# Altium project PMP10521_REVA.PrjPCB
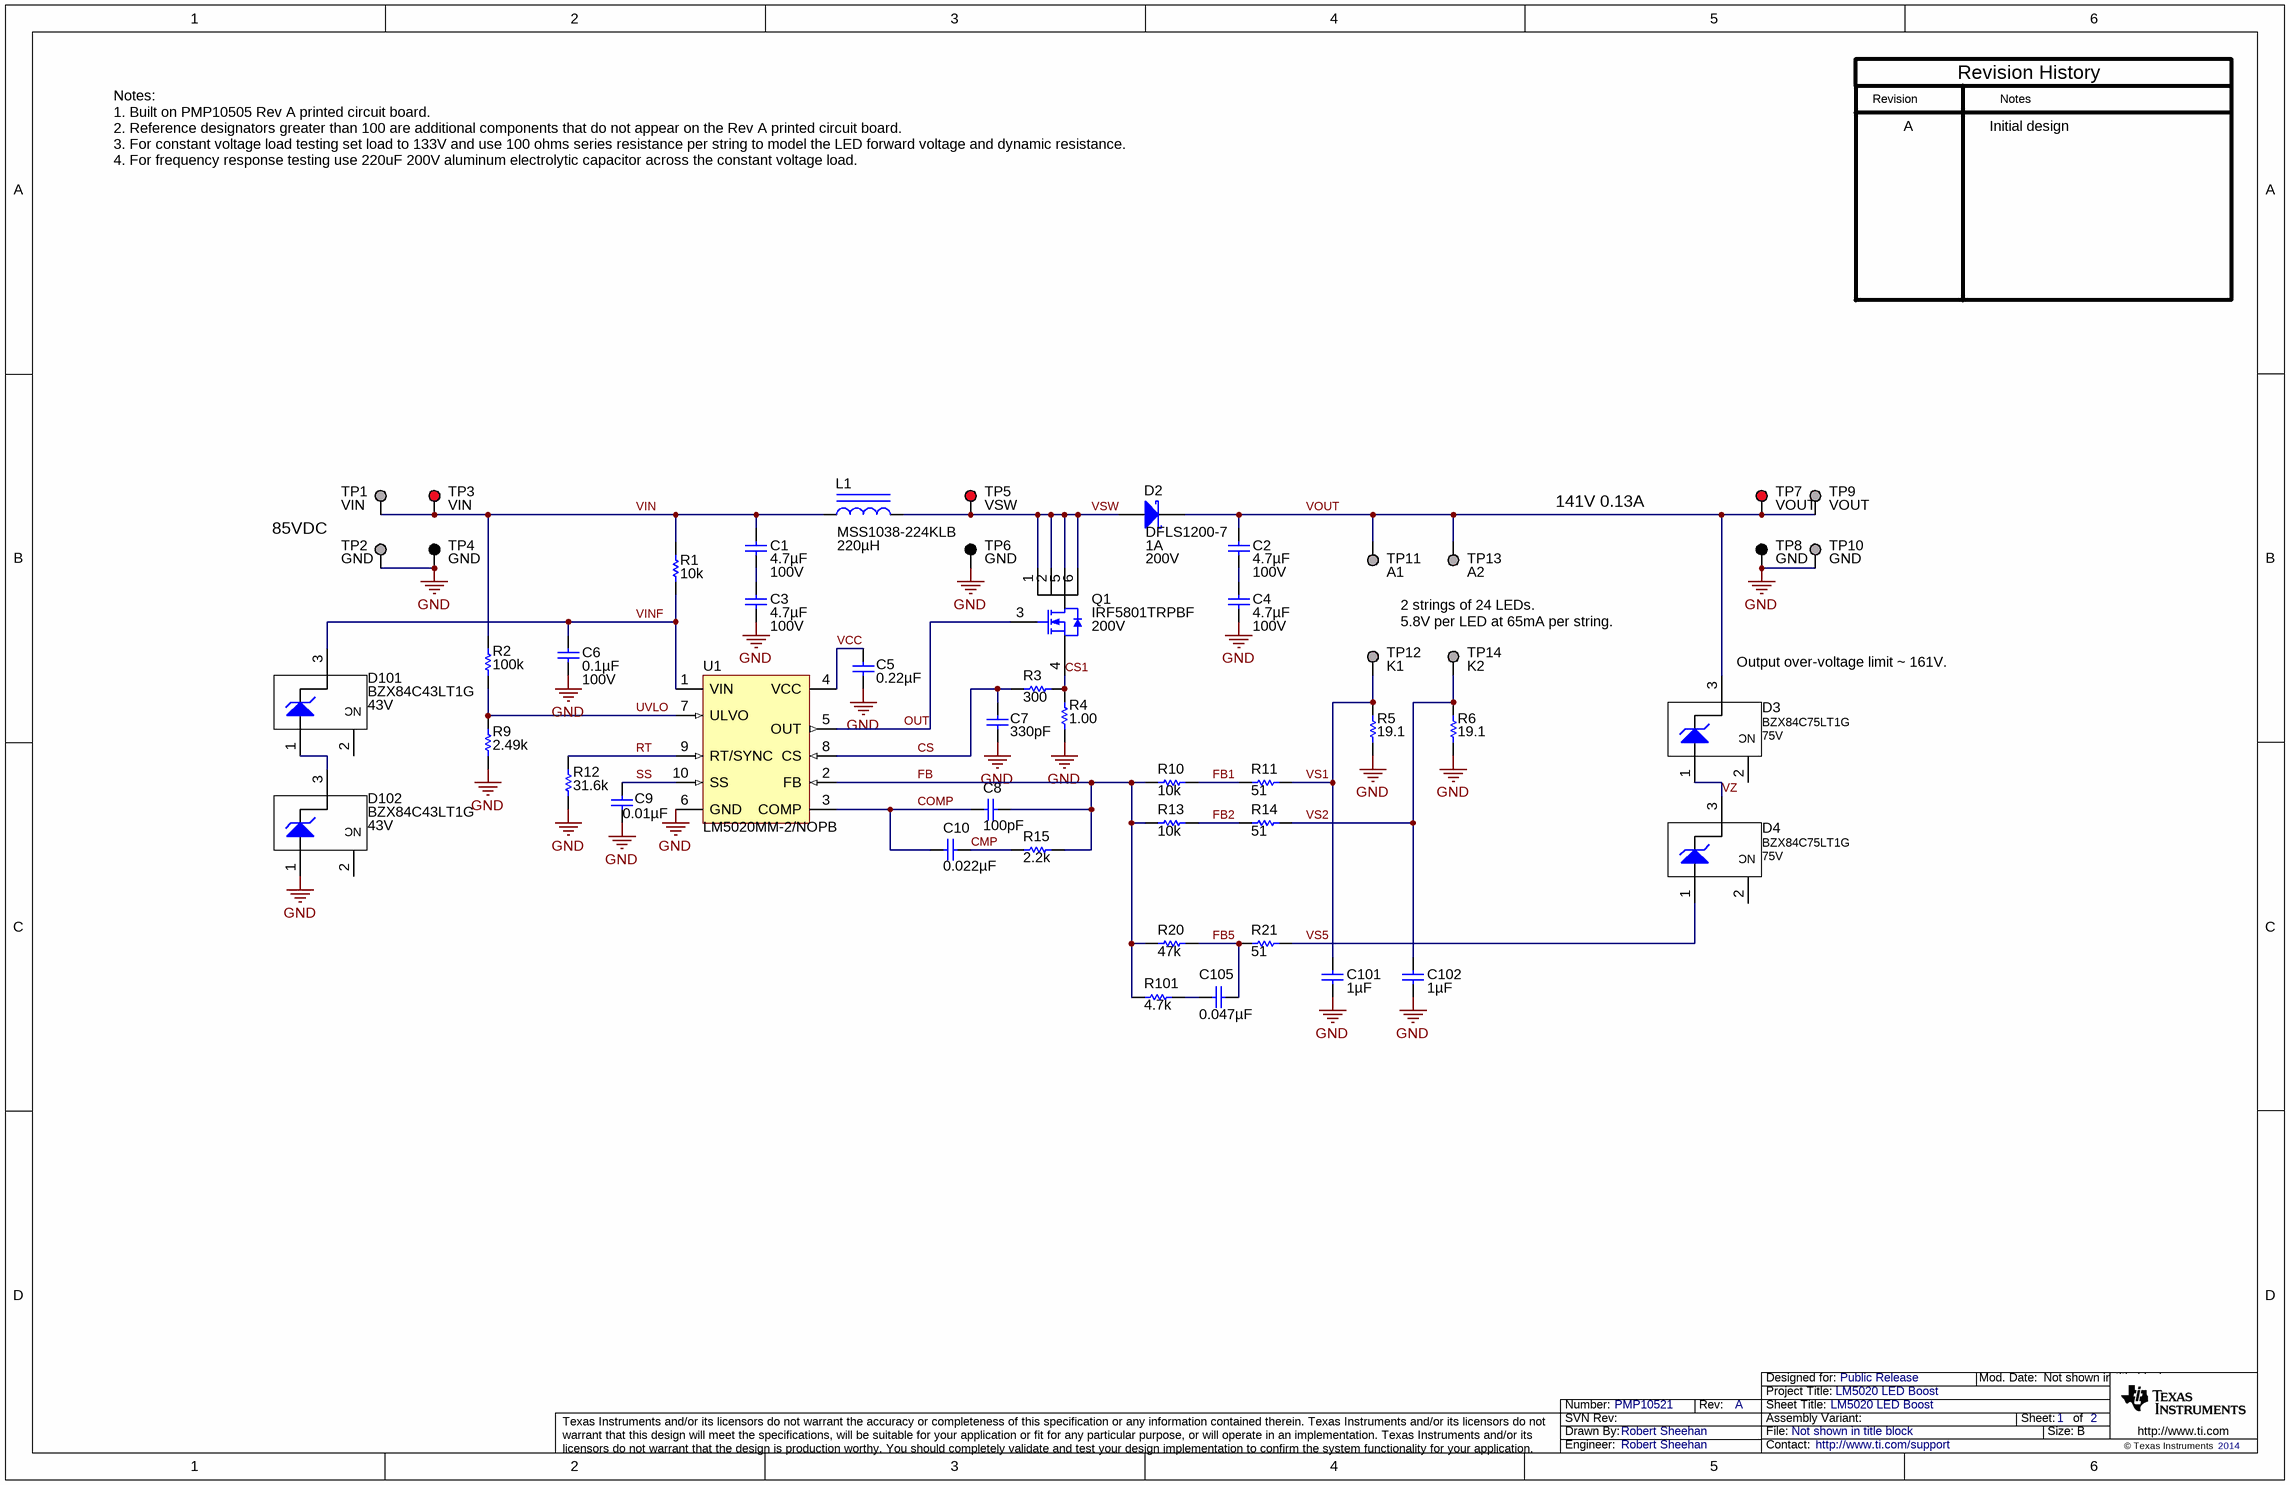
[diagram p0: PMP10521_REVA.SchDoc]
TechSupport: http://www.ti.com/support; SCH_Rev: A; PRJ_Title: LM5020 LED Boost; PRJ_Number: PMP10521; PRJ_Engineer: Robert Sheehan; PRJ_Customer: Public Release; PCB_Rev: A; PCB_Layout: Robert Sheehan; CopyrightYear: 2014
2 sheets, 69 parts. Net scope: global (net labels, ports and power ports of the same name join across sheets).
Board file: PMP10505_REVA.PcbDoc
Sheets:
  PMP10521_REVA.SchDoc
  PMP10521_REVA_Hardware.SchDoc

## Sheet PMP10521_REVA.SchDoc: LM5020 LED Boost
size 431 x 279 mm; Date: Not shown in title block; ApprovedBy: Not shown in title block; CheckedBy: Not shown in title block; Author: Not shown in title block; CompanyName: Not shown in title block; DrawnBy: Robert Sheehan; Engineer: Not shown in title block; Organization: Not shown in title block; Address1: Not shown in title block; Address2: Not shown in title block; Address3: Not shown in title block; Address4: Not shown in title block; DocumentNumber: 1; Revision: Use project parameter SCH_Rev; SheetNumber: 1; SheetTotal: 2; PageSetup: Record=PageOptions|CenterHorizontal=True|CenterVertical=True|PrintScale=1.00|XCorrection=1.00|YCorrection=1.00|PrintKind=0|BorderSize=5000000|LeftOffset=0|BottomOffset=0|Orientation=2|PaperLength=1000|PaperWidth=1000|Scale=100|PaperSource=15|PrintQuality=600|MediaType=1|DitherType=10|PaperKind=Letter|PrintScaleMode=1

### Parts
C1  ValueDisplayed: 4.7µF  Value2: 100V  [1210]  (hidden comment: C3225X7S2A475K200AB)
C2  ValueDisplayed: 4.7µF  Value2: 100V  [1210]  (hidden comment: C3225X7S2A475K200AB)
C3  ValueDisplayed: 4.7µF  Value2: 100V  [1210]  (hidden comment: C3225X7S2A475K200AB)
C4  ValueDisplayed: 4.7µF  Value2: 100V  [1210]  (hidden comment: C3225X7S2A475K200AB)
C5  ValueDisplayed: 0.22µF  [0603]  (hidden comment: GRM188R71C224KA01D)
C6  ValueDisplayed: 0.1µF  Value2: 100V  [0603]  (hidden comment: GRM188R72A104KA35D)
C7  ValueDisplayed: 330pF  [0603]  (hidden comment: GRM188R71H331KA01D)
C8  ValueDisplayed: 100pF  [0603]  (hidden comment: GRM1885C1H101JA01D)
C9  ValueDisplayed: 0.01µF  [0603]  (hidden comment: GRM188R71H103KA01D)
C10  ValueDisplayed: 0.022µF  [0603]  (hidden comment: GRM188R71H223KA01D)
C101  ValueDisplayed: 1µF  [0805_HV]  (hidden comment: GRM21BR71E105KA99L)
C102  ValueDisplayed: 1µF  [0805_HV]  (hidden comment: GRM21BR71E105KA99L)
C105  ValueDisplayed: 0.047µF  [0603]  (hidden comment: GRM188R71H473KA61D)
D2  DFLS1200-7  value 200V  Value1: 1A  [powerDI123]
D3  BZX84C75LT1G  value 75V  [SOT-23]
D4  BZX84C75LT1G  value 75V  [SOT-23]
D101  BZX84C43LT1G  value 43V  [SOT-23]
D102  BZX84C43LT1G  value 43V  [SOT-23]
L1  MSS1038-224KLB  ValueDisplayed: 220µH  [MSS1038]
Q1  IRF5801TRPBF  value 200V  [TSOP-6]
R1  value 10k  [0603]  (hidden comment: CRCW060310K0JNEA)
R2  value 100k  [0603]  (hidden comment: CRCW0603100KFKEA)
R3  value 300  [0603]  (hidden comment: CRCW0603300RJNEA)
R4  value 1.00  [0805_HV]  (hidden comment: CRCW08051R00FKEA)
R5  value 19.1  [1206]  (hidden comment: CRCW120619R1FKEA)
R6  value 19.1  [1206]  (hidden comment: CRCW120619R1FKEA)
R9  value 2.49k  [0603]  (hidden comment: CRCW06032K49FKEA)
R10  value 10k  [0603]  (hidden comment: CRCW060310K0JNEA)
R11  value 51  [0603]  (hidden comment: CRCW060351R0JNEA)
R12  value 31.6k  [0603]  (hidden comment: CRCW060331K6FKEA)
R13  value 10k  [0603]  (hidden comment: CRCW060310K0JNEA)
R14  value 51  [0603]  (hidden comment: CRCW060351R0JNEA)
R15  value 2.2k  [0603]  (hidden comment: CRCW06032K20JNEA)
R20  value 47k  [0603]  (hidden comment: CRCW060347K0JNEA)
R21  value 51  [0603]  (hidden comment: CRCW060351R0JNEA)
R101  value 4.7k  [0603]  (hidden comment: CRCW06034K70JNEA)
TP1  VIN  [Keystone1598-2]
TP2  GND  [Keystone1598-2]
TP3  VIN  [Keystone5010]
TP4  GND  [Keystone5011]
TP5  VSW  [Keystone5010]
TP6  GND  [Keystone5011]
TP7  VOUT  [Keystone5010]
TP8  GND  [Keystone5011]
TP9  VOUT  [Keystone1598-2]
TP10  GND  [Keystone1598-2]
TP11  A1  [Keystone1598-2]
TP12  K1  [Keystone1598-2]
TP13  A2  [Keystone1598-2]
TP14  K2  [Keystone1598-2]
U1  LM5020MM-2/NOPB  [MUB10A_N]

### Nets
GND: C3.2 C4.2 C5.2 C6.2 C7.2 C9.2 C101.2 C102.2 D102.1(A) R4.1 R5.1 R6.1 R9.1 R12.1 TP2.1 TP4.1 TP6.1 TP8.1 TP10.1 U1.6(GND)
CMP: C10.1 R15.1
COMP: C8.2 C10.2 U1.3(COMP)
CS: C7.1 R3.1 U1.8(CS)
CS1: Q1.4(S) R3.2 R4.2
FB: C8.1 R10.1 R13.1 R15.2 R20.1 R101.1 U1.2(FB)
FB1: R10.2 R11.1
FB2: R13.2 R14.1
FB5: C105.1 R20.2 R21.1
OUT: Q1.3(G) U1.5(OUT)
RT: R12.2 U1.9(RT/SYNC)
SS: C9.1 U1.10(SS)
UVLO: R2.1 R9.2 U1.7(ULVO)
VCC: C5.1 U1.4(VCC)
VIN: C1.1 L1.1 R1.2 R2.2 TP1.1 TP3.1
VINF: C6.1 D101.3(K) R1.1 U1.1(VIN)
VOUT: C2.1 D2.1(K) D3.3(K) TP7.1 TP9.1 TP11.1 TP13.1
VS1: C101.1 R5.2 R11.2 TP12.1
VS2: C102.1 R6.2 R14.2 TP14.1
VS5: D4.1(A) R21.2
VSW: D2.2(A) L1.2 Q1.1(D) Q1.2(D) Q1.5(D) Q1.6(D) TP5.1
VZ: D3.1(A) D4.3(K)
NetC1_2: C1.2 C3.1
NetC2_2: C2.2 C4.1
NetC105_2: C105.2 R101.2
NetD101_1: D101.1(A) D102.3(K)

Not connected (* = marked no-connect by the designer): D3 2(NC); D4 2(NC); D101 2(NC); D102 2(NC)

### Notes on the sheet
- Revision
- Notes
- Revision History
- A
- Initial design
- Notes:
  1. Built on PMP10505 Rev A printed circuit board.
  2. Reference designators greater than 100 are additional components that do not appear on the Rev A printed circuit board.
  3. For constant voltage load testing set load to 133V and use 100 ohms series resistance per string to model the LED forward voltage and dynamic resistance.
  4. For frequency response testing use 220uF 200V aluminum electrolytic capacitor across the constant voltage load.
- 141V 0.13A
- 85VDC
- 2 strings of 24 LEDs.
  5.8V per LED at 65mA per string.
- (near D3) Output over-voltage limit ~ 161V.

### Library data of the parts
C1-C4 = C3225X7S2A475K200AB: CAP, CERM, 4.7uF, 100V, +/-10%, X7S, 1210; Manufacturer: TDK; Polarized: N; CompType: Capacitor; U/M: EA; Cap_F: 0.0000047; Tolerance_%: 10; Value1: Unknown; VDC_V: 100; TaMin_C: -55; TaMax_C: 125
C5 = GRM188R71C224KA01D: CAP, CERM, 0.22uF, 16V, +/-10%, X7R, 0603; Manufacturer: MuRata; Polarized: N; CompType: Capacitor; U/M: EA; Cap_F: 0.00000022; Tolerance_%: 10; Value1: Unknown; VDC_V: 16; TaMin_C: -55; TaMax_C: 125
C6 = GRM188R72A104KA35D: CAP, CERM, 0.1uF, 100V, +/-10%, X7R, 0603; Manufacturer: MuRata; Polarized: N; CompType: Capacitor; U/M: EA; Cap_F: 0.0000001; Tolerance_%: 10; Value1: Unknown; VDC_V: 100; TaMin_C: -55; TaMax_C: 125
C7 = GRM188R71H331KA01D: CAP, CERM, 330pF, 50V, +/-10%, X7R, 0603; Manufacturer: MuRata; Polarized: N; CompType: Capacitor; U/M: EA; Cap_F: 0.00000000033; Tolerance_%: 10; Value1: Unknown; VDC_V: 50; TaMin_C: -55; TaMax_C: 125
C8 = GRM1885C1H101JA01D: CAP, CERM, 100pF, 50V, +/-5%, C0G/NP0, 0603; Manufacturer: MuRata; Polarized: N; CompType: Capacitor; U/M: EA; Cap_F: 0.0000000001; Tolerance_%: 5; Value1: Unknown; VDC_V: 50; TaMin_C: -55; TaMax_C: 125
C9 = GRM188R71H103KA01D: CAP, CERM, 0.01uF, 50V, +/-10%, X7R, 0603; Manufacturer: MuRata; Polarized: N; CompType: Capacitor; U/M: EA; Cap_F: 0.00000001; Tolerance_%: 10; Value1: Unknown; VDC_V: 50; TaMin_C: -55; TaMax_C: 125
C10 = GRM188R71H223KA01D: CAP, CERM, 0.022uF, 50V, +/-10%, X7R, 0603; Manufacturer: MuRata; Polarized: N; CompType: Capacitor; U/M: EA; Cap_F: 0.000000022; Tolerance_%: 10; Value1: Unknown; VDC_V: 50; TaMin_C: -55; TaMax_C: 125
C101 C102 = GRM21BR71E105KA99L: CAP, CERM, 1uF, 25V, +/-10%, X7R, 0805; Manufacturer: MuRata; Polarized: N; CompType: Capacitor; U/M: EA; Cap_F: 0.000001; Tolerance_%: 10; Value1: Unknown; VDC_V: 25; TaMin_C: -55; TaMax_C: 125; Cap_Case: 0805
C105 = GRM188R71H473KA61D: CAP, CERM, 0.047uF, 50V, +/-10%, X7R, 0603; Manufacturer: MuRata; Polarized: N; CompType: Capacitor; U/M: EA; Cap_F: 0.000000047; Tolerance_%: 10; Value1: Unknown; VDC_V: 50; TaMin_C: -55; TaMax_C: 125
D2 = DFLS1200-7: Diode, Schottky, 200V, 1A, PowerDI123; Manufacturer: Diodes Inc.; U/M: EA; Vf_V: 0.85; Value2: 0.85V; Io_A: 1; Vr_V: 200; TJmax_C: 175; RJC_CperW: 7
D3 D4 = BZX84C75LT1G: Diode, Zener, 75V, 225mW, SOT-23; Manufacturer: ON Semiconductor; U/M: EA; Power_W: 0.225; Vz_V: 75; Value1: 0.225W; RJA_CperW: 556
D101 D102 = BZX84C43LT1G: Diode, Zener, 43V, 225mW, SOT-23; Manufacturer: ON Semiconductor; U/M: EA; Power_W: 0.225; Vz_V: 43; Value1: 0.225W; RJA_CperW: 556
L1 = MSS1038-224KLB: Inductor, Shielded Drum Core, Ferrite, 220uH, 0.97A, 0.76 ohm, SMD; Manufacturer: Coilcraft; Ind_H: 220.0E-6; Imax_A: 0.97; Irms: 0.97A @ 40C rise; Isat: 0.99A @ 30% inductance drop; DCR_ohm: 0.76
Q1 = IRF5801TRPBF: MOSFET, N-CH, 200V, 0.6A, TSOP-6; Manufacturer: International Rectifier; Alternate Manufacturer: None; U/M: EA; ChType: N; VdsMax_V: 200; Value1: ? ohm; Value2: 3.9 nC; QgTyp_nC: 3.9; Vgs_V: 30; IdsMax_A: 0.6; SymbolCreator: x0208325
R1 R10 R13 = CRCW060310K0JNEA: RES, 10k ohm, 5%, 0.1W, 0603; Manufacturer: Vishay-Dale; CompType: Resistor; Res_ohm: 10000; Value_Code: 10k0; Tolerance_%: 5; Power_W: 0.1; VDC_V: 75; TempCo: 200 ppm/C; EIA_Code: E24; U/M: EA
R2 = CRCW0603100KFKEA: RES, 100k ohm, 1%, 0.1W, 0603; Manufacturer: Vishay-Dale; CompType: Resistor; Res_ohm: 100000; Tolerance_%: 1; Power_W: 0.1; VDC_V: 75; TempCo: 100 ppm/C; EIA_Code: E96; U/M: EA
R3 = CRCW0603300RJNEA: RES, 300 ohm, 5%, 0.1W, 0603; Manufacturer: Vishay-Dale; CompType: Resistor; Value_Code: 300R; Tolerance_%: 5; Power_W: 0.1; VDC_V: 75; TempCo: 200 ppm/C; EIA_Code: E24; U/M: EA
R4 = CRCW08051R00FKEA: RES, 1.00 ohm, 1%, 0.125W, 0805; Manufacturer: Vishay-Dale; CompType: Resistor; Res_ohm: 1; Value_Code: 1R00; Power_W: 0.125; VDC_V: 150; TempCo: 100 ppm/C; EIA_Code: E96; U/M: EA
R5 R6 = CRCW120619R1FKEA: RES, 19.1 ohm, 1%, 0.25W, 1206; Manufacturer: Vishay-Dale; CompType: Resistor; Value_Code: 19R1; Tolerance_%: 1; Power_W: 0.25; VDC_V: 200; TempCo: 100 ppm/C; EIA_Code: E96; U/M: EA
R9 = CRCW06032K49FKEA: RES, 2.49k ohm, 1%, 0.1W, 0603; Manufacturer: Vishay-Dale; CompType: Resistor; Res_ohm: 2490; Value_Code: 2k49; Tolerance_%: 1; Power_W: 0.1; VDC_V: 75; TempCo: 100 ppm/C; EIA_Code: E96; U/M: EA
R11 R14 R21 = CRCW060351R0JNEA: RES, 51 ohm, 5%, 0.1W, 0603; Manufacturer: Vishay-Dale; CompType: Resistor; Value_Code: 51R0; Tolerance_%: 5; Power_W: 0.1; VDC_V: 75; TempCo: 200 ppm/C; EIA_Code: E24; U/M: EA
R12 = CRCW060331K6FKEA: RES, 31.6k ohm, 1%, 0.1W, 0603; Manufacturer: Vishay-Dale; CompType: Resistor; Res_ohm: 31600; Value_Code: 31k6; Tolerance_%: 1; Power_W: 0.1; VDC_V: 75; TempCo: 100 ppm/C; EIA_Code: E96; U/M: EA
R15 = CRCW06032K20JNEA: RES, 2.2k ohm, 5%, 0.1W, 0603; Manufacturer: Vishay-Dale; CompType: Resistor; Res_ohm: 2200; Value_Code: 2k20; Tolerance_%: 5; Power_W: 0.1; VDC_V: 75; TempCo: 200 ppm/C; EIA_Code: E24; U/M: EA
R20 = CRCW060347K0JNEA: RES, 47k ohm, 5%, 0.1W, 0603; Manufacturer: Vishay-Dale; CompType: Resistor; Res_ohm: 47000; Value_Code: 47k0; Tolerance_%: 5; Power_W: 0.1; VDC_V: 75; TempCo: 200 ppm/C; EIA_Code: E24; U/M: EA
R101 = CRCW06034K70JNEA: RES, 4.7k ohm, 5%, 0.1W, 0603; Manufacturer: Vishay-Dale; CompType: Resistor; Res_ohm: 4700; Value_Code: 4k70; Tolerance_%: 5; Power_W: 0.1; VDC_V: 75; TempCo: 200 ppm/C; EIA_Code: E24; U/M: EA
TP1 TP2 TP9-TP14 = 1598-2: Terminal, Turret, TH, Triple; Manufacturer: Keystone; CompType: Turret Terminal; U/M: EA
TP3 TP5 TP7 = 5010: Test Point, Multipurpose, Red, TH; Manufacturer: Keystone; CompType: Test Point Loop; U/M: EA
TP4 TP6 TP8 = 5011: Test Point, Multipurpose, Black, TH; Manufacturer: Keystone; CompType: Test Point Loop; U/M: EA
U1 = LM5020MM-2/NOPB: 100V Current Mode PWM Controller, 10-pin MSOP, Pb-Free; Manufacturer: Texas Instruments; PackageTopMarking: ZXTT*SBNB; PowerWise: Y; CompType: Switcher

## Sheet PMP10521_REVA_Hardware.SchDoc: LM5020 LED Boost Hardware
size 431 x 279 mm; Date: Not shown in title block; ApprovedBy: Not shown in title block; CheckedBy: Not shown in title block; Author: Not shown in title block; CompanyName: Not shown in title block; DrawnBy: Robert Sheehan; Engineer: Not shown in title block; Organization: Not shown in title block; Address1: Not shown in title block; Address2: Not shown in title block; Address3: Not shown in title block; Address4: Not shown in title block; DocumentNumber: 2; Revision: Use project parameter SCH_Rev; SheetNumber: 2; SheetTotal: 2; PageSetup: Record=PageOptions|CenterHorizontal=True|CenterVertical=True|PrintScale=1.00|XCorrection=1.00|YCorrection=1.00|PrintKind=0|BorderSize=5000000|LeftOffset=0|BottomOffset=0|Orientation=2|PaperLength=1000|PaperWidth=1000|Scale=100|PaperSource=15|PrintQuality=600|MediaType=1|DitherType=10|PaperKind=Letter|PrintScaleMode=1
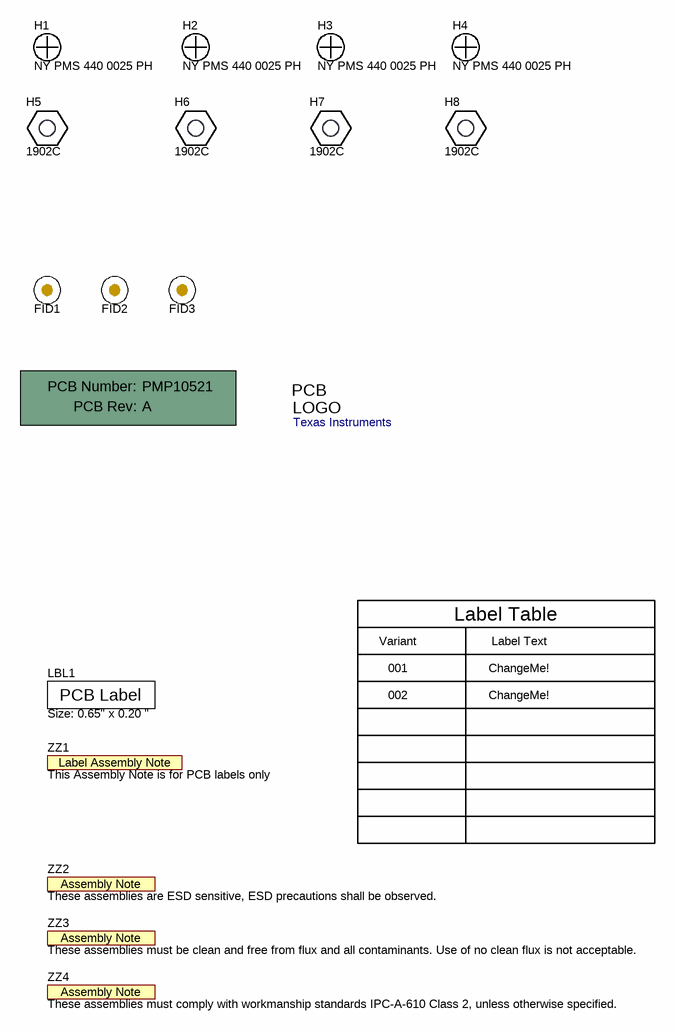
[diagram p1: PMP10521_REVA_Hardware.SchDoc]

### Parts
!PCB1  Printed Circuit Board  (value not drawn)  (mechanical)
FID1  Fiducial  [Fiducial10-20]  (value not drawn)
FID2  Fiducial  [Fiducial10-20]  (value not drawn)
FID3  Fiducial  [Fiducial10-20]  (value not drawn)
H1  NY PMS 440 0025 PH  [NY PMS 440 0025 PH]
H2  NY PMS 440 0025 PH  [NY PMS 440 0025 PH]
H3  NY PMS 440 0025 PH  [NY PMS 440 0025 PH]
H4  NY PMS 440 0025 PH  [NY PMS 440 0025 PH]
H5  1902C  [Keystone_1902C]
H6  1902C  [Keystone_1902C]
H7  1902C  [Keystone_1902C]
H8  1902C  [Keystone_1902C]
LBL1  Size: 0.65" x 0.20 "  [Label_650x200]
Logo1  Texas Instruments  [TI_Stacked_SolderMask_Small]  (no BOM)
ZZ1  This Assembly Note is for PCB labels only  [AssemblyNoteLabel]  (no BOM)
ZZ2  These assemblies are ESD sensitive, ESD precautions shall be observed.  [AssemblyNote]  (no BOM)
ZZ3  These assemblies must be clean and free from flux and all contaminants. Use of no clean flux is not acceptable.  [AssemblyNote]  (no BOM)
ZZ4  These assemblies must comply with workmanship standards IPC-A-610 Class 2, unless otherwise specified.  [AssemblyNote]  (no BOM)

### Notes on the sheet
- Variant
- Label Table
- Label Text
- 001
- 002
- ChangeMe!

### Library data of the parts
!PCB1 = PCB: Manufacturer: Any; PartNumber: PMP10521; SymbolCreator: a0412235
FID1-FID3 = Fiducial: Fiducial mark.  There is nothing to buy or mount.; SymbolCreator: codlsc
H1-H4 = NY PMS 440 0025 PH: Machine Screw, Round, #4-40 x 1/4, Nylon, Philips panhead; Manufacturer: B&F Fastener Supply; CompType: Hardware; SymbolCreator: codlsc; U/M: EA
H5-H8 = 1902C: Standoff, Hex, 0.5"L #4-40 Nylon; Manufacturer: Keystone; CompType: Hardware; SymbolCreator: a0412235
LBL1 = THT-14-423-10: Thermal Transfer Printable Labels, 0.650" W x 0.200" H - 10,000 per roll; Manufacturer: Brady; SymbolCreator: a0412235; CompType: Label
Logo1 = TI_Logo: Texas Instrument Corporate Signature; SymbolCreator: a0412235
ZZ1 = AssemblyNoteLabel: SymbolCreator: a0412235
ZZ2-ZZ4 = AssemblyNote: SymbolCreator: codlsc

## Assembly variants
001: not fitted FID1 FID2 FID3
